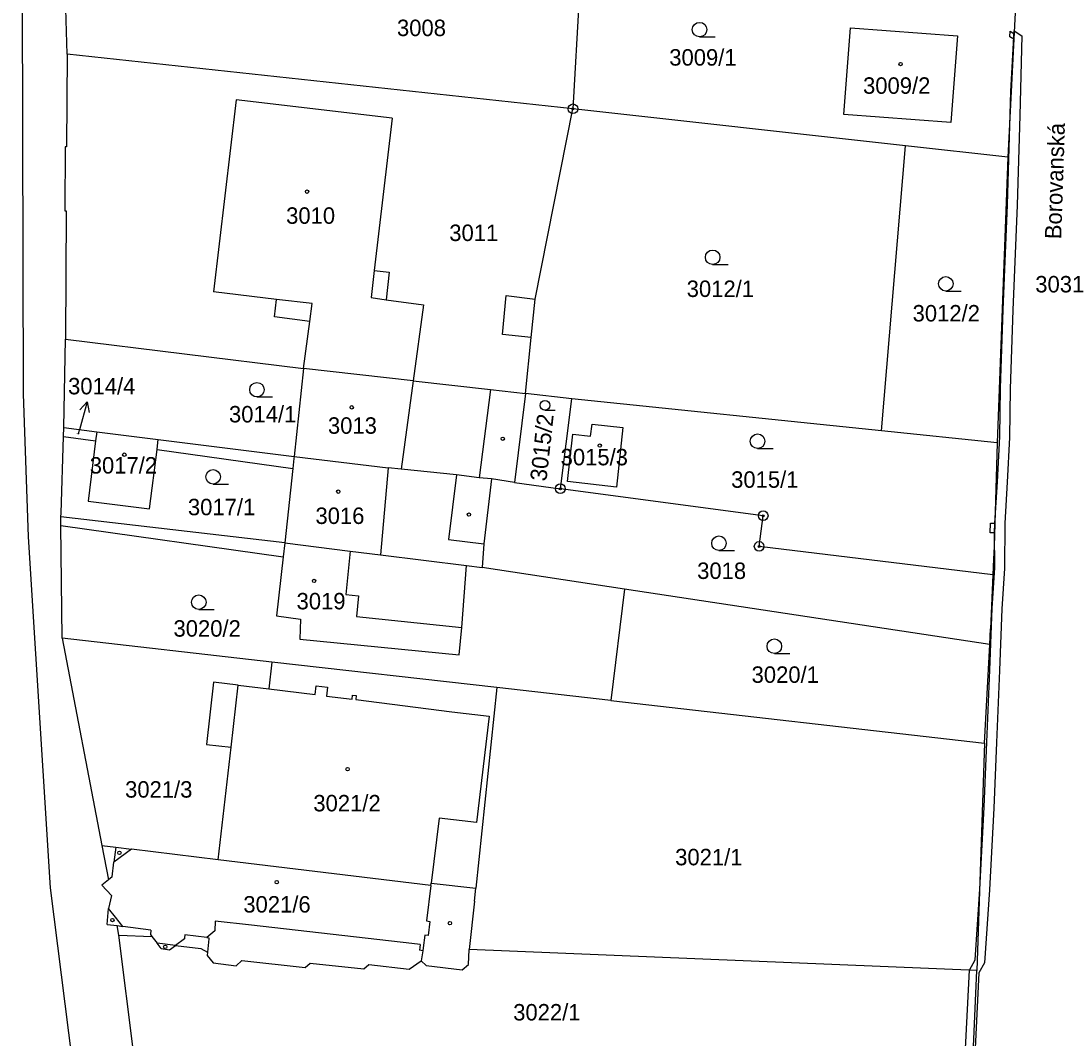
# Model space of a CAD drawing. Extents: x -755819 to -753140, y -1169796 to -1166000.
# Drawn here: x -754210.5 to -754102.6, y -1169236.7 to -1169131.6 of the extents above; entities that cross this region are included whole.
import ezdxf

# ---------------------------------------------------------------- set-up
doc = ezdxf.new("R2010")
doc.units = 0
for name, color, linetype in [('Vrstva 1', 7, 'Continuous'), ('Vrstva 15', 7, 'Continuous'), ('Vrstva 16', 7, 'Continuous'), ('Vrstva 18', 7, 'Continuous'), ('Vrstva 19', 7, 'Continuous'), ('Vrstva 24', 7, 'Continuous'), ('Vrstva 25', 7, 'Continuous'), ('Vrstva 27', 7, 'Continuous'), ('Vrstva 4', 7, 'Continuous'), ('Vrstva 6', 7, 'Continuous')]:
    doc.layers.add(name, color=color, linetype=linetype)

msp = doc.modelspace()

# ---------------------------------------------------------------- linework, layer by layer
at = {"layer": 'Vrstva 1'}
for p, q in [((-754210.27, -1169170.11), (-754210.54, -1169067.62)), ((-754205.76, -1169135.04), (-754206.15, -1169121.55)), ((-754152.67, -1169125.06), (-754153.53, -1169140.67)), ((-754107.8, -1169129.35), (-754108.63, -1169145.66)), ((-754125.55, -1169141.26), (-754124.87, -1169132.29)), ((-754124.87, -1169132.29), (-754113.82, -1169133.13)), ((-754113.82, -1169133.13), (-754114.51, -1169142.1)), ((-754205.76, -1169135.04), (-754205.82, -1169144.6)), ((-754153.53, -1169140.67), (-754205.76, -1169135.04)), ((-754188.3, -1169139.76), (-754190.64, -1169159.59)), ((-754172.19, -1169141.63), (-754188.3, -1169139.76)), ((-754157.44, -1169160.34), (-754153.53, -1169140.67)), ((-754119.17, -1169144.49), (-754153.53, -1169140.67)), ((-754172.19, -1169141.63), (-754174.04, -1169157.36)), ((-754114.51, -1169142.1), (-754125.55, -1169141.26)), ((-754205.97, -1169144.6), (-754206.01, -1169151.21)), ((-754205.82, -1169144.6), (-754205.97, -1169144.6)), ((-754108.63, -1169145.66), (-754119.17, -1169144.49)), ((-754108.63, -1169145.66), (-754109.73, -1169175.19)), ((-754206.01, -1169151.21), (-754205.86, -1169151.21)), ((-754205.86, -1169151.21), (-754205.94, -1169164.48)), ((-754174.04, -1169157.36), (-754172.5, -1169157.54)), ((-754172.5, -1169157.54), (-754172.82, -1169160.39)), ((-754184.14, -1169160.36), (-754190.64, -1169159.59)), ((-754184.35, -1169162.15), (-754184.14, -1169160.36)), ((-754172.82, -1169160.39), (-754168.96, -1169160.92)), ((-754168.96, -1169160.92), (-754170.03, -1169168.77)), ((-754157.86, -1169164.3), (-754157.44, -1169160.34)), ((-754180.7, -1169162.63), (-754184.35, -1169162.15)), ((-754181.34, -1169167.5), (-754180.7, -1169162.63)), ((-754206.11, -1169173.61), (-754205.94, -1169164.48)), ((-754205.94, -1169164.48), (-754181.34, -1169167.5)), ((-754158.42, -1169170.08), (-754157.86, -1169164.3)), ((-754181.34, -1169167.5), (-754182.33, -1169176.58)), ((-754170.03, -1169168.77), (-754181.34, -1169167.5)), ((-754170.03, -1169168.77), (-754162.03, -1169169.67)), ((-754162.03, -1169169.67), (-754158.42, -1169170.08)), ((-754209.76, -1169184.89), (-754210.27, -1169170.11)), ((-754158.42, -1169170.08), (-754159.56, -1169179.28)), ((-754153.66, -1169170.64), (-754158.42, -1169170.08)), ((-754154.83, -1169179.92), (-754153.66, -1169170.64)), ((-754121.65, -1169173.94), (-754153.66, -1169170.64)), ((-754206.14, -1169174.52), (-754206.11, -1169173.61)), ((-754206.11, -1169173.61), (-754202.7, -1169174.04)), ((-754202.7, -1169174.04), (-754202.82, -1169174.98)), ((-754202.7, -1169174.04), (-754196.35, -1169174.83)), ((-754154.1, -1169179.18), (-754153.54, -1169174.27)), ((-754153.54, -1169174.27), (-754151.7, -1169174.48)), ((-754151.7, -1169174.48), (-754151.54, -1169173.24)), ((-754151.54, -1169173.24), (-754148.36, -1169173.6)), ((-754148.36, -1169173.6), (-754149.04, -1169179.74)), ((-754109.73, -1169175.19), (-754121.65, -1169173.94)), ((-754206.39, -1169182.44), (-754206.14, -1169174.52)), ((-754202.82, -1169174.98), (-754203.61, -1169181.22)), ((-754196.48, -1169175.87), (-754196.39, -1169175.14)), ((-754196.39, -1169175.14), (-754196.35, -1169174.83)), ((-754109.73, -1169175.19), (-754110.04, -1169185.88)), ((-754197.25, -1169182.01), (-754196.48, -1169175.87)), ((-754182.35, -1169176.79), (-754182.46, -1169177.82)), ((-754182.33, -1169176.58), (-754182.35, -1169176.79)), ((-754182.33, -1169176.58), (-754172.62, -1169177.76)), ((-754182.46, -1169177.82), (-754183.3, -1169185.52)), ((-754171.27, -1169177.9), (-754172.62, -1169177.76)), ((-754165.55, -1169178.47), (-754171.27, -1169177.9)), ((-754163.22, -1169178.78), (-754165.55, -1169178.47)), ((-754161.93, -1169178.91), (-754163.22, -1169178.78)), ((-754161.93, -1169178.91), (-754162.72, -1169185.6)), ((-754159.56, -1169179.28), (-754161.93, -1169178.91)), ((-754159.56, -1169179.28), (-754154.83, -1169179.92)), ((-754149.04, -1169179.74), (-754154.1, -1169179.18)), ((-754133.88, -1169182.71), (-754154.83, -1169179.92)), ((-754203.61, -1169181.22), (-754197.25, -1169182.01)), ((-754206.4, -1169182.82), (-754206.39, -1169182.44)), ((-754206.4, -1169183.72), (-754206.4, -1169182.82)), ((-754134.3, -1169185.88), (-754133.88, -1169182.71)), ((-754206.27, -1169195.34), (-754206.4, -1169183.72)), ((-754207.5, -1169221.13), (-754209.76, -1169184.89)), ((-754183.3, -1169185.52), (-754183.46, -1169186.96)), ((-754183.3, -1169185.52), (-754176.53, -1169186.36)), ((-754162.72, -1169185.6), (-754162.89, -1169188.04)), ((-754110.15, -1169188.82), (-754134.3, -1169185.88)), ((-754110.04, -1169185.88), (-754110.08, -1169187.18)), ((-754183.46, -1169186.96), (-754184.15, -1169193.05)), ((-754176.53, -1169186.36), (-754173.4, -1169186.75)), ((-754173.4, -1169186.75), (-754164.53, -1169187.84)), ((-754110.08, -1169187.18), (-754110.15, -1169188.82)), ((-754164.99, -1169194.26), (-754164.53, -1169187.84)), ((-754164.53, -1169187.84), (-754162.89, -1169188.04)), ((-754110.15, -1169188.82), (-754110.4, -1169194.39)), ((-754148.2, -1169190.3), (-754149.61, -1169201.8)), ((-754184.15, -1169193.05), (-754181.65, -1169193.4)), ((-754181.65, -1169193.4), (-754181.75, -1169195.45)), ((-754165.27, -1169197.08), (-754164.99, -1169194.26)), ((-754110.48, -1169196), (-754110.4, -1169194.39)), ((-754184.62, -1169197.84), (-754206.27, -1169195.34)), ((-754206.27, -1169195.34), (-754202.19, -1169216.77)), ((-754181.75, -1169195.45), (-754165.27, -1169197.08)), ((-754111.01, -1169206.2), (-754110.48, -1169196)), ((-754184.62, -1169197.84), (-754184.92, -1169200.6)), ((-754161.39, -1169200.46), (-754184.62, -1169197.84)), ((-754188.83, -1169206.63), (-754188.09, -1169200.21)), ((-754188.09, -1169200.21), (-754184.92, -1169200.6)), ((-754161.39, -1169200.46), (-754163.56, -1169221.17)), ((-754149.61, -1169201.8), (-754161.39, -1169200.46)), ((-754149.61, -1169201.8), (-754111.01, -1169206.2)), ((-754190.16, -1169218.24), (-754188.83, -1169206.63)), ((-754111.01, -1169206.2), (-754111.81, -1169229.68)), ((-754202.19, -1169216.77), (-754200.75, -1169216.95)), ((-754202.19, -1169216.77), (-754201.51, -1169220.32)), ((-754200.75, -1169216.95), (-754199.12, -1169217.15)), ((-754190.16, -1169218.24), (-754199.12, -1169217.15)), ((-754168.21, -1169220.92), (-754190.16, -1169218.24)), ((-754201.51, -1169220.32), (-754202.19, -1169220.86)), ((-754168.21, -1169220.92), (-754168.18, -1169220.68)), ((-754168.18, -1169220.68), (-754163.56, -1169221.17)), ((-754204.16, -1169247.33), (-754207.5, -1169221.13)), ((-754202.19, -1169220.86), (-754201.2, -1169221.93)), ((-754163.7, -1169222.54), (-754163.56, -1169221.17)), ((-754201.2, -1169221.93), (-754201.49, -1169223.29)), ((-754163.7, -1169222.54), (-754164.26, -1169227.53)), ((-754201.64, -1169224.92), (-754201.49, -1169223.29)), ((-754201.64, -1169224.92), (-754200.61, -1169225.05)), ((-754200.42, -1169226.04), (-754200.61, -1169225.05)), ((-754198.87, -1169238.36), (-754200.42, -1169226.04)), ((-754200.42, -1169226.04), (-754197.01, -1169226.18)), ((-754197.01, -1169226.18), (-754196.47, -1169226.86)), ((-754196.07, -1169227.41), (-754196.47, -1169226.86)), ((-754195.18, -1169227.54), (-754194.57, -1169227.09)), ((-754194.57, -1169227.09), (-754191.97, -1169227.41)), ((-754196.07, -1169227.41), (-754195.18, -1169227.54)), ((-754191.97, -1169227.41), (-754191.26, -1169227.8)), ((-754191.26, -1169227.8), (-754191.29, -1169228.13)), ((-754191.29, -1169228.13), (-754190.68, -1169228.9)), ((-754164.31, -1169229.08), (-754164.26, -1169227.53)), ((-754111.81, -1169229.68), (-754164.26, -1169227.53)), ((-754190.68, -1169228.9), (-754188.31, -1169229.19)), ((-754188.31, -1169229.19), (-754187.72, -1169228.65)), ((-754187.72, -1169228.65), (-754181.2, -1169229.37)), ((-754181.2, -1169229.37), (-754180.68, -1169228.92)), ((-754180.68, -1169228.92), (-754175.12, -1169229.53)), ((-754175.12, -1169229.53), (-754174.62, -1169229.08)), ((-754174.62, -1169229.08), (-754170.43, -1169229.56)), ((-754170.43, -1169229.56), (-754169.2, -1169228.69)), ((-754169.2, -1169228.69), (-754168.69, -1169229.18)), ((-754168.69, -1169229.18), (-754164.98, -1169229.61)), ((-754164.98, -1169229.61), (-754164.31, -1169229.08)), ((-754112.35, -1169241.92), (-754111.81, -1169229.68))]:
    msp.add_line(p, q, dxfattribs=at)
at = {"layer": 'Vrstva 16'}
for p in [(-754203.71, -1169170.93), (-754204.6, -1169174.27)]:
    msp.add_line(p, (-754204.48, -1169173.83), dxfattribs=at)
msp.add_lwpolyline([(-754204.45, -1169171.77), (-754203.71, -1169170.93), (-754203.48, -1169172.03)], dxfattribs=at)
at = {"layer": 'Vrstva 24'}
for centre, radius in [((-754153.53, -1169140.67), 0.5), ((-754153.53, -1169140.67), 0.1), ((-754154.83, -1169179.92), 0.5), ((-754154.83, -1169179.92), 0.1), ((-754133.88, -1169182.71), 0.5), ((-754133.88, -1169182.71), 0.1), ((-754134.3, -1169185.88), 0.5), ((-754134.3, -1169185.88), 0.1)]:
    msp.add_circle(centre, radius, dxfattribs=at)
at = {"layer": 'Vrstva 25'}
for p, q in [((-754140.45, -1169133.24), (-754138.85, -1169133.24)), ((-754139.1, -1169156.76), (-754137.5, -1169156.76)), ((-754115.02, -1169159.5), (-754113.42, -1169159.5)), ((-754186.16, -1169170.44), (-754184.56, -1169170.44)), ((-754156.42, -1169171.81), (-754155.35, -1169171.81)), ((-754134.46, -1169175.76), (-754132.86, -1169175.76)), ((-754190.69, -1169179.44), (-754189.09, -1169179.44)), ((-754138.45, -1169186.3), (-754136.85, -1169186.3)), ((-754192.17, -1169192.39), (-754190.57, -1169192.39)), ((-754132.73, -1169196.94), (-754131.13, -1169196.94))]:
    msp.add_line(p, q, dxfattribs=at)
for centre, radius in [((-754140.45, -1169132.49), 0.75), ((-754119.69, -1169136.05), 0.175), ((-754180.98, -1169149.23), 0.175), ((-754139.1, -1169156.01), 0.75), ((-754115.02, -1169158.75), 0.75), ((-754186.16, -1169169.69), 0.75), ((-754156.42, -1169171.31), 0.503), ((-754176.37, -1169171.51), 0.175), ((-754134.46, -1169175.01), 0.75), ((-754160.78, -1169174.76), 0.175), ((-754150.76, -1169175.46), 0.175), ((-754199.86, -1169176.4), 0.175), ((-754190.69, -1169178.69), 0.75), ((-754177.77, -1169180.22), 0.175), ((-754164.27, -1169182.59), 0.175), ((-754138.45, -1169185.55), 0.75), ((-754180.26, -1169189.44), 0.175), ((-754192.17, -1169191.64), 0.75), ((-754132.73, -1169196.19), 0.75), ((-754176.8, -1169208.89), 0.175), ((-754200.37, -1169217.53), 0.175), ((-754184.12, -1169220.56), 0.175), ((-754201.09, -1169224.48), 0.175), ((-754166.23, -1169224.8), 0.175), ((-754195.63, -1169227.24), 0.175)]:
    msp.add_circle(centre, radius, dxfattribs=at)
at = {"layer": 'Vrstva 27'}
for p, q in [((-754108.41, -1169133.23), (-754108.37, -1169132.64)), ((-754108.01, -1169133.49), (-754108.41, -1169133.23)), ((-754108.37, -1169132.64), (-754107.98, -1169132.9)), ((-754108.29, -1169138.89), (-754107.97, -1169132.62)), ((-754107.98, -1169132.9), (-754108.01, -1169133.49)), ((-754107.97, -1169132.62), (-754107.16, -1169133.15)), ((-754107.16, -1169133.15), (-754107.36, -1169141.35)), ((-754108.65, -1169150.59), (-754108.29, -1169138.89)), ((-754107.36, -1169141.35), (-754107.65, -1169150.63)), ((-754109.11, -1169161.44), (-754108.65, -1169150.59)), ((-754107.65, -1169150.63), (-754108.11, -1169161.48)), ((-754109.39, -1169169.53), (-754109.11, -1169161.44)), ((-754108.11, -1169161.48), (-754108.39, -1169169.59)), ((-754109.45, -1169174.53), (-754109.39, -1169169.53)), ((-754108.39, -1169169.59), (-754108.45, -1169174.61)), ((-754109.7, -1169179.19), (-754109.45, -1169174.53)), ((-754108.45, -1169174.61), (-754108.7, -1169179.25)), ((-754109.97, -1169183.47), (-754109.7, -1169179.19)), ((-754108.7, -1169179.25), (-754108.93, -1169183.46)), ((-754110.43, -1169184.46), (-754110.4, -1169183.46)), ((-754110.4, -1169183.46), (-754109.97, -1169183.47)), ((-754109.97, -1169183.47), (-754110, -1169184.47)), ((-754110, -1169184.47), (-754109.97, -1169183.47)), ((-754108.93, -1169183.46), (-754108.97, -1169188.16)), ((-754110, -1169184.47), (-754110.43, -1169184.46)), ((-754109.97, -1169188.1), (-754110, -1169184.47)), ((-754110.24, -1169192.24), (-754109.97, -1169188.1)), ((-754108.97, -1169188.16), (-754109.24, -1169192.32)), ((-754110.49, -1169198.67), (-754110.24, -1169192.24)), ((-754109.24, -1169192.32), (-754109.49, -1169198.71)), ((-754110.78, -1169206.1), (-754110.49, -1169198.67)), ((-754109.49, -1169198.71), (-754109.78, -1169206.14)), ((-754111.06, -1169212.8), (-754110.78, -1169206.1)), ((-754109.78, -1169206.14), (-754110.06, -1169212.92)), ((-754111.52, -1169221.29), (-754111.06, -1169212.8)), ((-754110.06, -1169212.92), (-754110.52, -1169221.35)), ((-754111.99, -1169228.58), (-754111.52, -1169221.29)), ((-754110.52, -1169221.35), (-754111.01, -1169228.88)), ((-754112.58, -1169229.65), (-754111.99, -1169228.58)), ((-754111.01, -1169228.88), (-754111.6, -1169229.92)), ((-754113.14, -1169240.54), (-754112.58, -1169229.65)), ((-754111.6, -1169229.92), (-754112.12, -1169240.26))]:
    msp.add_line(p, q, dxfattribs=at)
at = {"layer": 'Vrstva 4'}
for p, q in [((-754174.04, -1169157.36), (-754174.37, -1169160.18)), ((-754174.37, -1169160.18), (-754172.82, -1169160.39)), ((-754160.82, -1169163.98), (-754160.41, -1169159.97)), ((-754160.41, -1169159.97), (-754157.44, -1169160.34)), ((-754180.46, -1169160.79), (-754184.14, -1169160.36)), ((-754180.7, -1169162.63), (-754180.46, -1169160.79)), ((-754157.86, -1169164.3), (-754160.82, -1169163.98)), ((-754170.03, -1169168.77), (-754171.27, -1169177.9)), ((-754162.03, -1169169.67), (-754163.22, -1169178.78)), ((-754196.35, -1169174.83), (-754182.33, -1169176.58)), ((-754172.62, -1169177.76), (-754173.4, -1169186.75)), ((-754165.55, -1169178.47), (-754166.37, -1169185.17)), ((-754183.3, -1169185.52), (-754206.4, -1169182.82)), ((-754166.37, -1169185.17), (-754162.72, -1169185.6)), ((-754176.53, -1169186.36), (-754177, -1169190.83)), ((-754177, -1169190.83), (-754175.66, -1169190.97)), ((-754175.66, -1169190.97), (-754175.89, -1169193.11)), ((-754175.89, -1169193.11), (-754164.99, -1169194.26)), ((-754190.64, -1169199.91), (-754191.36, -1169206.34)), ((-754188.09, -1169200.21), (-754190.64, -1169199.91)), ((-754184.92, -1169200.6), (-754180.15, -1169201.19)), ((-754180.15, -1169201.19), (-754180.04, -1169200.28)), ((-754180.04, -1169200.28), (-754178.87, -1169200.42)), ((-754178.87, -1169200.42), (-754178.98, -1169201.33)), ((-754176.34, -1169201.65), (-754176.29, -1169201.25)), ((-754176.29, -1169201.25), (-754175.9, -1169201.29)), ((-754178.98, -1169201.33), (-754176.34, -1169201.65)), ((-754175.9, -1169201.29), (-754175.95, -1169201.69)), ((-754175.95, -1169201.69), (-754166.03, -1169202.95)), ((-754166.03, -1169202.95), (-754162.17, -1169203.4)), ((-754162.17, -1169203.4), (-754163.5, -1169214.41)), ((-754191.36, -1169206.34), (-754188.83, -1169206.63)), ((-754167.36, -1169213.94), (-754168.18, -1169220.68)), ((-754163.5, -1169214.41), (-754167.36, -1169213.94)), ((-754200.75, -1169216.95), (-754200.95, -1169218.49)), ((-754199.12, -1169217.15), (-754200.95, -1169218.49)), ((-754201.12, -1169220), (-754200.95, -1169218.49)), ((-754201.12, -1169220), (-754201.51, -1169220.32)), ((-754168.21, -1169220.92), (-754168.64, -1169224.57)), ((-754200.78, -1169224.17), (-754201.49, -1169223.29)), ((-754200, -1169225.13), (-754200.78, -1169224.17)), ((-754190.49, -1169224.6), (-754190.5, -1169225.6)), ((-754186.72, -1169225.02), (-754190.49, -1169224.6)), ((-754168.64, -1169224.57), (-754168.31, -1169224.61)), ((-754168.31, -1169224.61), (-754168.48, -1169226.08)), ((-754200.61, -1169225.05), (-754200, -1169225.13)), ((-754197.12, -1169225.53), (-754200, -1169225.13)), ((-754197.12, -1169225.53), (-754197.16, -1169225.98)), ((-754197.16, -1169225.98), (-754197.01, -1169226.18)), ((-754193.61, -1169226), (-754193.65, -1169226.32)), ((-754191.33, -1169226.29), (-754193.61, -1169226)), ((-754190.5, -1169225.6), (-754191.33, -1169226.29)), ((-754170.15, -1169226.9), (-754186.72, -1169225.02)), ((-754168.81, -1169226.04), (-754168.99, -1169227.33)), ((-754168.48, -1169226.08), (-754168.81, -1169226.04)), ((-754194.57, -1169227.09), (-754196.47, -1169226.86)), ((-754193.66, -1169226.43), (-754194.57, -1169227.09)), ((-754193.65, -1169226.32), (-754193.66, -1169226.43)), ((-754191.33, -1169226.29), (-754191.13, -1169226.31)), ((-754191.14, -1169226.42), (-754191.26, -1169227.8)), ((-754191.13, -1169226.31), (-754191.14, -1169226.42)), ((-754169.31, -1169227), (-754170.15, -1169226.9)), ((-754169.31, -1169227), (-754169.35, -1169227.32)), ((-754169.35, -1169227.32), (-754169.38, -1169227.6)), ((-754169.02, -1169227.65), (-754169.38, -1169227.6)), ((-754169.02, -1169227.65), (-754169.2, -1169228.69)), ((-754168.99, -1169227.33), (-754169.02, -1169227.65))]:
    msp.add_line(p, q, dxfattribs=at)
at = {"layer": 'Vrstva 6'}
for p, q in [((-754121.65, -1169173.94), (-754119.17, -1169144.49)), ((-754206.14, -1169174.52), (-754202.82, -1169174.98)), ((-754196.48, -1169175.87), (-754182.46, -1169177.82)), ((-754206.4, -1169183.72), (-754183.46, -1169186.96)), ((-754148.2, -1169190.3), (-754162.89, -1169188.04)), ((-754110.48, -1169196), (-754148.2, -1169190.3))]:
    msp.add_line(p, q, dxfattribs=at)

# ---------------------------------------------------------------- texts
at = {"layer": 'Vrstva 15'}
msp.add_text('Borovanská', height=1.7, rotation=88.1782, dxfattribs=at).set_placement((-754103.1, -1169154.16))
at = {"layer": 'Vrstva 16'}
msp.add_text('3014/4', height=1.7, dxfattribs=at).set_placement((-754205.67, -1169170.17))
at = {"layer": 'Vrstva 18'}
for s, height, p in [('3008', 1.7, (-754171.7, -1169133.16)), ('3009/1', 1.7, (-754143.58, -1169136.21)), ('3011', 1.7, (-754166.3, -1169154.33)), ('3031', 1.7, (-754105.78, -1169159.64)), ('3012/1', 1.7, (-754141.78, -1169160.11)), ('3012/2', 1.7, (-754118.45, -1169162.64)), ('3014/1', 1.7, (-754189.05, -1169173.07)), ('3014/4', 0.1, (-754204.83, -1169174.27)), ('3015/1', 1.7, (-754137.19, -1169179.82)), ('3017/1', 1.7, (-754193.29, -1169182.66)), ('3018', 1.7, (-754140.7, -1169189.24)), ('3020/2', 1.7, (-754194.78, -1169195.2)), ('3020/1', 1.7, (-754135.08, -1169199.97)), ('3021/3', 1.7, (-754199.78, -1169211.83)), ('3021/1', 1.7, (-754142.97, -1169218.82)), ('3022/1', 1.7, (-754159.7, -1169234.85))]:
    msp.add_text(s, height=height, dxfattribs=at).set_placement(p)
msp.add_text('3015/2', height=1.7, rotation=83.7091, dxfattribs=at).set_placement((-754156.27, -1169179.2))
at = {"layer": 'Vrstva 19'}
for s, p in [('3009/2', (-754123.57, -1169139.12)), ('3010', (-754183.15, -1169152.55)), ('3013', (-754178.83, -1169174.24)), ('3015/3', (-754154.8, -1169177.5)), ('3017/2', (-754203.43, -1169178.35)), ('3016', (-754180.12, -1169183.56)), ('3019', (-754182.07, -1169192.38)), ('3021/2', (-754180.34, -1169213.25)), ('3021/6', (-754187.57, -1169223.7))]:
    msp.add_text(s, height=1.7, dxfattribs=at).set_placement(p)

doc.saveas('drawing.dxf')
